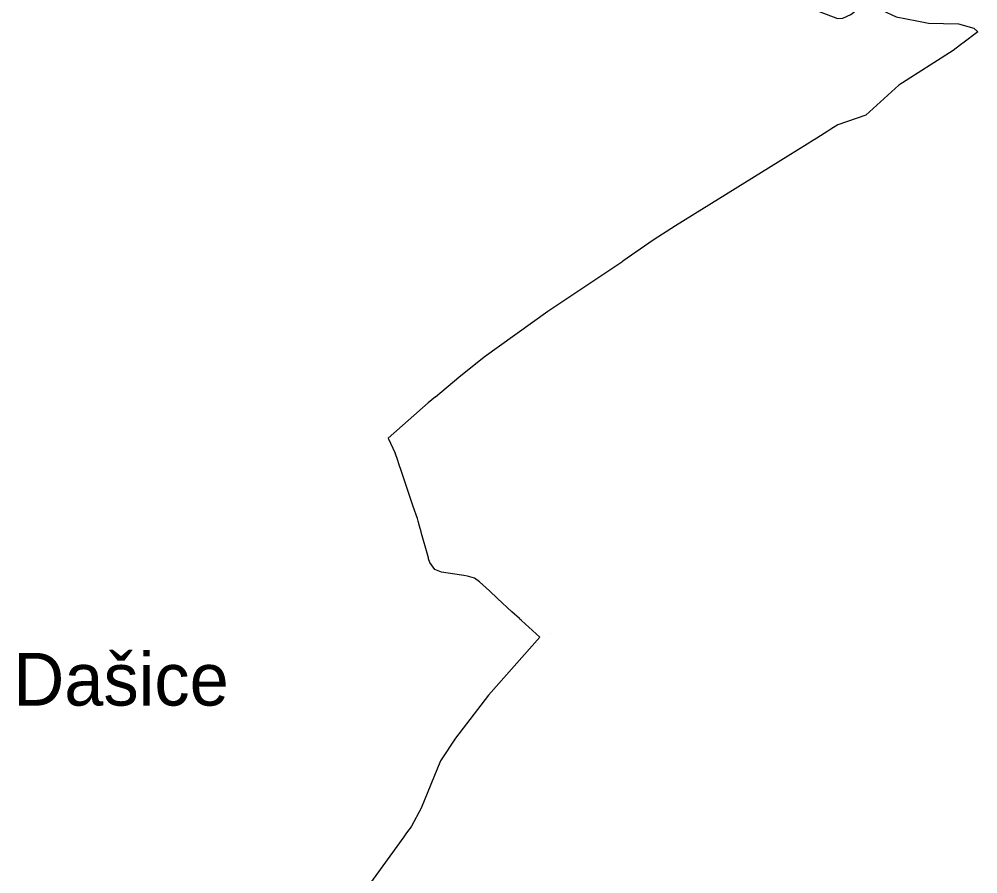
# Model space of a CAD drawing. Extents: x -637021 to -633415, y -1065012 to -1061066.
# Drawn here: x -636954 to -635863, y -1063011 to -1062038 of the extents above; entities that cross this region are included whole.
import ezdxf

# ---------------------------------------------------------------- set-up
doc = ezdxf.new("R2010")
doc.units = 0
doc.layers.add('KU_OST', color=7, linetype='Continuous')
doc.layers.add('OVNE_PRE', color=7, linetype='Continuous')

msp = doc.modelspace()

# ---------------------------------------------------------------- linework, layer by layer
at = {"layer": 'OVNE_PRE'}
for p, q in [((-636057.3, -1062180.8), (-636079, -1062194.4)), ((-636050, -1062176.2), (-636057.3, -1062180.8)), ((-636232.3, -1062290.1), (-636267, -1062313.7)), ((-636480.1, -1062468.1), (-636488.6, -1062475.2)), ((-636488.6, -1062475.2), (-636534, -1062515.4)), ((-636534, -1062515.4), (-636526, -1062532.2)), ((-636349.8, -1062737.2), (-636349.8, -1062737.2))]:
    msp.add_line(p, q, dxfattribs=at)
for points in [[(-636144.2, -1061988.4), (-636116.3, -1062001.2), (-636048.6, -1062027.7), (-636043.5, -1062029.7), (-636022.6, -1062037.9), (-636016.6, -1062037.4), (-636007.3, -1062033.2), (-635986.4, -1062016.2), (-635972.2, -1062028.1), (-635955.8, -1062035.7), (-635932.4, -1062040.3), (-635918.9, -1062043), (-635885, -1062043.9), (-635867.6, -1062048.8), (-635862.9, -1062053), (-635864.4, -1062054.1), (-635878.3, -1062064.5), (-635882.5, -1062067.7), (-635891.1, -1062074.1), (-635952.7, -1062113.4)], [(-635952.7, -1062113.4), (-635990.3, -1062147.7), (-636022.4, -1062158.9), (-636030.2, -1062163.7), (-636033.8, -1062166), (-636046.2, -1062173.8), (-636049.1, -1062175.6), (-636050, -1062176.2)], [(-636079, -1062194.4), (-636207, -1062273.8), (-636232.3, -1062290.1)], [(-636425, -1062422.7), (-636352.3, -1062370.8), (-636267, -1062313.7)], [(-636480.1, -1062468.1), (-636453.7, -1062445.9), (-636425, -1062422.7)], [(-636500.8, -1062606.6), (-636505.5, -1062592.8), (-636520.1, -1062549.8), (-636520.8, -1062547.7), (-636524.3, -1062537.1), (-636526, -1062532.2)], [(-636480.8, -1062664.5), (-636486.8, -1062656.7), (-636488, -1062652.5), (-636488.3, -1062651.4), (-636489, -1062648.8), (-636496, -1062623.8), (-636496.6, -1062621.9), (-636498.3, -1062615.5), (-636500, -1062609.7), (-636500.8, -1062606.6)], [(-636361.5, -1062741.7), (-636382.3, -1062722.7), (-636384.1, -1062721.1), (-636384.7, -1062720.5), (-636393.2, -1062712.7), (-636409.5, -1062697.7), (-636418.8, -1062689.1), (-636430.3, -1062678.6), (-636435.7, -1062674.7), (-636443.9, -1062672.1), (-636448, -1062671.5), (-636450.6, -1062671.1), (-636473.5, -1062667.8), (-636480.8, -1062664.5)], [(-636361.5, -1062741.7), (-636419.9, -1062807.8), (-636457.5, -1062856.4), (-636474.5, -1062882.4), (-636496.5, -1062936.1), (-636507.6, -1062956.7), (-636509.1, -1062958.8), (-636510.8, -1062961.1), (-636513.9, -1062965.4), (-636516.3, -1062968.8)], [(-636513.9, -1062965.4), (-636516.3, -1062968.8), (-636595.9, -1063079), (-636598.3, -1063082.3), (-636576.1, -1063114.5), (-636565.8, -1063120.7), (-636560.6, -1063122.7)]]:
    msp.add_lwpolyline(points, dxfattribs=at)

# ---------------------------------------------------------------- texts
at = {"layer": 'KU_OST'}
msp.add_text('Dašice', height=60, dxfattribs=at).set_placement((-636960.7, -1062819.5))

doc.saveas('drawing.dxf')
